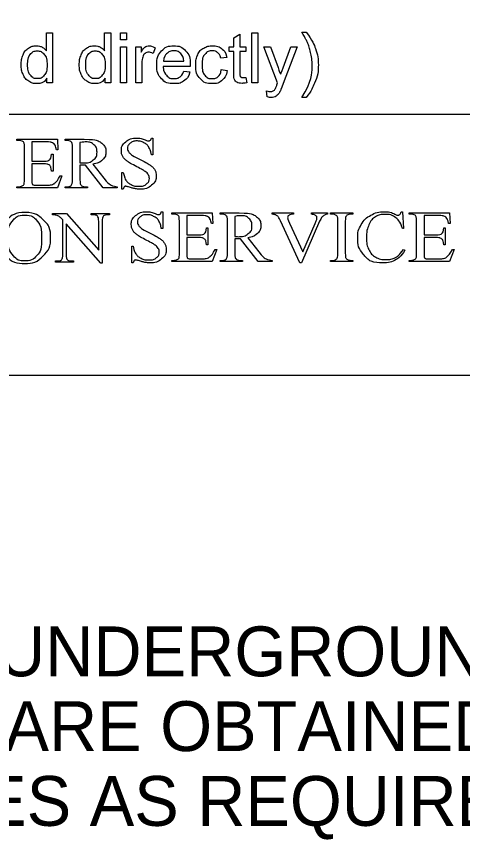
# Model space of a CAD drawing. Extents: x 0 to 34, y 0 to 22.
# Drawn here: x 5.69 to 6.942, y 7.479 to 9.791 of the extents above; entities that cross this region are included whole.
import ezdxf

# ---------------------------------------------------------------- set-up
doc = ezdxf.new("R2010")
doc.units = 0
doc.layers.add('SH_Data', color=7, linetype='Continuous')
doc.layers.add('SH_Text', color=7, linetype='Continuous')

msp = doc.modelspace()

# ---------------------------------------------------------------- linework, layer by layer
at = {"layer": 'SH_Data'}
msp.add_line((2.2617, 9.5165), (7.4617, 9.5165), dxfattribs=at)
msp.add_lwpolyline([(2.2617, 11.8822), (7.4617, 11.8822), (7.4617, 8.7822), (2.2617, 8.7822)], close=True, dxfattribs=at)
msp.add_lwpolyline([(2.2617, 11.8822), (7.4617, 11.8822), (7.4617, 8.7822), (2.2617, 8.7822)], close=True, dxfattribs=at)
for points in [[(5.7741, 9.6943), (5.7741, 9.7445), (5.7913, 9.7445), (5.7913, 9.6045), (5.7754, 9.6045)], [(5.9372, 9.6943), (5.9372, 9.7445), (5.9544, 9.7445), (5.9544, 9.6045), (5.9385, 9.6045)], [(5.9815, 9.7248), (5.9815, 9.7445), (5.9987, 9.7445), (5.9987, 9.7248), (5.9815, 9.7248)], [(6.2996, 9.6342), (6.2996, 9.6927), (6.2869, 9.6927), (6.2869, 9.706), (6.2996, 9.706), (6.2996, 9.7311), (6.3167, 9.7414), (6.3167, 9.706), (6.3339, 9.706), (6.3339, 9.6927), (6.3167, 9.6927), (6.3167, 9.6332)], [(6.3504, 9.6045), (6.3504, 9.7445), (6.3675, 9.7445), (6.3675, 9.6045), (6.3504, 9.6045)], [(6.491, 9.7469), (6.5033, 9.7469)], [(5.9815, 9.6045), (5.9815, 9.706), (5.9987, 9.706), (5.9987, 9.6045), (5.9815, 9.6045)], [(6.0246, 9.6045), (6.0246, 9.706), (6.0401, 9.706), (6.0401, 9.6906)], [(6.0796, 9.7028), (6.0736, 9.6868)], [(6.4229, 9.6044), (6.3844, 9.706), (6.4029, 9.706), (6.424, 9.6474)], [(6.4385, 9.6468), (6.4602, 9.706), (6.4774, 9.706), (6.4389, 9.6028)], [(6.1028, 9.6649), (6.1595, 9.6649)], [(6.2801, 9.6761), (6.2634, 9.6736)], [(6.0418, 9.6577), (6.0418, 9.6045), (6.0246, 9.6045)], [(6.1775, 9.6508), (6.1018, 9.6508)], [(6.2649, 9.6417), (6.2817, 9.6394)], [(5.7754, 9.6045), (5.7754, 9.6173)], [(5.9385, 9.6045), (5.9385, 9.6173)], [(6.1593, 9.6373), (6.177, 9.635)], [(6.3339, 9.6198), (6.3364, 9.6047)], [(6.3935, 9.5655), (6.3916, 9.5817)], [(6.5033, 9.5633), (6.491, 9.5633)], [(5.6966, 9.4424), (5.6914, 9.4424), (5.6914, 9.4461), (5.8048, 9.4461), (5.8063, 9.416), (5.8021, 9.416)], [(5.7332, 9.4386), (5.7332, 9.3846), (5.7655, 9.3846)], [(5.7736, 9.4386), (5.7332, 9.4386)], [(5.8319, 9.4424), (5.8264, 9.4424), (5.8264, 9.4461), (5.8798, 9.4461)], [(5.8681, 9.4365), (5.8681, 9.3795)], [(6.0725, 9.4492), (6.0725, 9.4019), (6.0685, 9.4019)], [(6.0685, 9.4492), (6.0725, 9.4492)], [(5.7124, 9.3335), (5.7124, 9.4223)], [(5.8474, 9.3335), (5.8474, 9.4218)], [(5.7887, 9.4045), (5.7926, 9.4045), (5.7926, 9.3567), (5.7887, 9.3567)], [(5.7655, 9.3771), (5.7332, 9.3771), (5.7332, 9.332)], [(5.8681, 9.3732), (5.8681, 9.3335)], [(5.9725, 9.3092), (5.9332, 9.3092), (5.8834, 9.3732)], [(5.9047, 9.3758), (5.9351, 9.3366)], [(5.813, 9.3435), (5.8174, 9.3435), (5.8047, 9.3092), (5.6914, 9.3092), (5.6914, 9.3129), (5.6966, 9.3129)], [(5.9899, 9.3061), (5.9859, 9.3061), (5.9859, 9.353), (5.9899, 9.353)], [(5.7453, 9.3167), (5.7703, 9.3167)], [(5.8834, 9.3129), (5.8891, 9.3129), (5.8891, 9.3092), (5.8264, 9.3092), (5.8264, 9.3129), (5.8319, 9.3129)], [(5.9725, 9.3129), (5.9725, 9.3092)], [(5.7911, 9.2374), (5.8308, 9.2374), (5.9208, 9.1347), (5.9208, 9.2137)], [(5.7911, 9.2337), (5.7911, 9.2374)], [(5.9051, 9.2337), (5.9, 9.2337), (5.9, 9.2374), (5.951, 9.2374), (5.951, 9.2337), (5.9458, 9.2337)], [(6.1004, 9.2423), (6.1004, 9.195), (6.0964, 9.195)], [(6.0964, 9.2423), (6.1004, 9.2423)], [(6.1315, 9.2355), (6.1263, 9.2355), (6.1263, 9.2391), (6.2396, 9.2391), (6.2412, 9.2091), (6.237, 9.2091)], [(6.1681, 9.2317), (6.1681, 9.1776), (6.2004, 9.1776)], [(6.2085, 9.2317), (6.1681, 9.2317)], [(6.2668, 9.2355), (6.2613, 9.2355), (6.2613, 9.2391), (6.3147, 9.2391)], [(6.303, 9.2295), (6.303, 9.1726)], [(6.4074, 9.2355), (6.4074, 9.2391), (6.4674, 9.2391), (6.4674, 9.2355)], [(6.5176, 9.2355), (6.5176, 9.2391), (6.5628, 9.2391)], [(6.5628, 9.2391), (6.5628, 9.2355)], [(6.5763, 9.2355), (6.5711, 9.2355), (6.5711, 9.2391), (6.6339, 9.2391), (6.6339, 9.2355), (6.6286, 9.2355)], [(6.7693, 9.2423), (6.7732, 9.2423)], [(6.7732, 9.2423), (6.7765, 9.1958), (6.7732, 9.1958)], [(6.7973, 9.2355), (6.7921, 9.2355), (6.7921, 9.2391), (6.9054, 9.2391), (6.907, 9.2091), (6.9028, 9.2091)], [(6.8339, 9.2317), (6.8339, 9.1776), (6.8662, 9.1776)], [(6.8743, 9.2317), (6.8339, 9.2317)], [(5.82, 9.1243), (5.82, 9.2194)], [(5.9303, 9.2137), (5.9303, 9.0983), (5.9264, 9.0983), (5.8295, 9.2086), (5.8295, 9.1243)], [(6.1473, 9.1265), (6.1473, 9.2153)], [(6.2823, 9.1265), (6.2823, 9.2149)], [(6.5408, 9.2157), (6.4897, 9.0991), (6.4857, 9.0991), (6.4307, 9.2172)], [(6.4561, 9.2105), (6.4935, 9.1302), (6.5281, 9.2095)], [(6.5921, 9.1265), (6.5921, 9.2149)], [(6.6129, 9.2149), (6.6129, 9.1265)], [(6.8131, 9.1265), (6.8131, 9.2153)], [(6.2236, 9.1975), (6.2275, 9.1975), (6.2275, 9.1498), (6.2236, 9.1498)], [(6.8894, 9.1975), (6.8933, 9.1975), (6.8933, 9.1498), (6.8894, 9.1498)], [(6.2004, 9.1701), (6.1681, 9.1701), (6.1681, 9.1251)], [(6.303, 9.1662), (6.303, 9.1265)], [(6.4074, 9.1023), (6.3681, 9.1023), (6.3183, 9.1662)], [(6.3396, 9.1689), (6.37, 9.1297)], [(6.8662, 9.1701), (6.8339, 9.1701), (6.8339, 9.1251)], [(6.0178, 9.0991), (6.0138, 9.0991), (6.0138, 9.1461), (6.0178, 9.1461)], [(6.2479, 9.1366), (6.2523, 9.1366), (6.2396, 9.1023), (6.1263, 9.1023), (6.1263, 9.106), (6.1315, 9.106)], [(6.7765, 9.1364), (6.7799, 9.1344)], [(6.9137, 9.1366), (6.9181, 9.1366), (6.9054, 9.1023), (6.7921, 9.1023), (6.7921, 9.106), (6.7973, 9.106)], [(6.1802, 9.1098), (6.2052, 9.1098)], [(6.846, 9.1098), (6.871, 9.1098)], [(5.8451, 9.1042), (5.8503, 9.1042), (5.8503, 9.1006), (5.7993, 9.1006), (5.7993, 9.1042), (5.8044, 9.1042)], [(6.3183, 9.106), (6.324, 9.106), (6.324, 9.1023), (6.2613, 9.1023), (6.2613, 9.106), (6.2668, 9.106)], [(6.4074, 9.106), (6.4074, 9.1023)], [(6.6339, 9.106), (6.6339, 9.1023), (6.5711, 9.1023), (6.5711, 9.106), (6.5763, 9.106)], [(6.6286, 9.106), (6.6339, 9.106)]]:
    msp.add_lwpolyline(points, dxfattribs=at)
for points in [[(6.491, 9.5633), (6.5195, 9.6092), (6.5195, 9.6551), (6.5195, 9.6731), (6.5154, 9.6907), (6.5122, 9.705), (6.5063, 9.7182), (6.5026, 9.7268), (6.491, 9.7469)], [(6.5033, 9.7469), (6.5212, 9.7229), (6.5298, 9.6987), (6.5372, 9.6779), (6.5372, 9.6552), (6.5372, 9.6294), (6.5273, 9.6053), (6.5174, 9.5813), (6.5033, 9.5633)], [(5.7754, 9.6173), (5.7658, 9.6023), (5.7471, 9.6023), (5.7349, 9.6023), (5.7247, 9.609), (5.7146, 9.6156), (5.709, 9.6276), (5.7034, 9.6396), (5.7034, 9.6552), (5.7034, 9.6703), (5.7084, 9.6827), (5.7135, 9.6951), (5.7236, 9.7017), (5.7337, 9.7082), (5.7462, 9.7082), (5.7554, 9.7082), (5.7625, 9.7044), (5.7697, 9.7005), (5.7741, 9.6943)], [(5.9385, 9.6173), (5.9288, 9.6023), (5.9101, 9.6023), (5.898, 9.6023), (5.8878, 9.609), (5.8776, 9.6156), (5.872, 9.6276), (5.8664, 9.6396), (5.8664, 9.6552), (5.8664, 9.6703), (5.8715, 9.6827), (5.8766, 9.6951), (5.8867, 9.7017), (5.8968, 9.7082), (5.9093, 9.7082), (5.9184, 9.7082), (5.9256, 9.7044), (5.9327, 9.7005), (5.9372, 9.6943)], [(6.0401, 9.6906), (6.046, 9.7014), (6.051, 9.7048), (6.056, 9.7082), (6.062, 9.7082), (6.0707, 9.7082), (6.0796, 9.7028)], [(6.177, 9.635), (6.1728, 9.6195), (6.1615, 9.6109), (6.1501, 9.6023), (6.1324, 9.6023), (6.1102, 9.6023), (6.0972, 9.616), (6.0841, 9.6297), (6.0841, 9.6544), (6.0841, 9.68), (6.0973, 9.6941), (6.1105, 9.7082), (6.1315, 9.7082), (6.1518, 9.7082), (6.1647, 9.6944), (6.1776, 9.6805), (6.1776, 9.6554), (6.1776, 9.6539), (6.1775, 9.6508)], [(6.2817, 9.6394), (6.279, 9.622), (6.2676, 9.6121), (6.2562, 9.6023), (6.2395, 9.6023), (6.2187, 9.6023), (6.2061, 9.6159), (6.1934, 9.6295), (6.1934, 9.6549), (6.1934, 9.6713), (6.1988, 9.6836), (6.2043, 9.6959), (6.2154, 9.7021), (6.2265, 9.7082), (6.2396, 9.7082), (6.2562, 9.7082), (6.2667, 9.6999), (6.2772, 9.6915), (6.2801, 9.6761)], [(5.7211, 9.6552), (5.7211, 9.6357), (5.7293, 9.626), (5.7375, 9.6164), (5.7487, 9.6164), (5.76, 9.6164), (5.7679, 9.6256), (5.7757, 9.6348), (5.7757, 9.6537), (5.7757, 9.6746), (5.7677, 9.6843), (5.7597, 9.694), (5.7479, 9.694), (5.7365, 9.694), (5.7288, 9.6847), (5.7211, 9.6753), (5.7211, 9.6552)], [(5.8842, 9.6552), (5.8842, 9.6357), (5.8924, 9.626), (5.9006, 9.6164), (5.9118, 9.6164), (5.923, 9.6164), (5.9309, 9.6256), (5.9388, 9.6348), (5.9388, 9.6537), (5.9388, 9.6746), (5.9308, 9.6843), (5.9227, 9.694), (5.911, 9.694), (5.8995, 9.694), (5.8918, 9.6847), (5.8842, 9.6753), (5.8842, 9.6552)], [(6.0736, 9.6868), (6.0674, 9.6905), (6.0611, 9.6905), (6.0555, 9.6905), (6.051, 9.6871), (6.0465, 9.6837), (6.0446, 9.6777), (6.0418, 9.6685), (6.0418, 9.6577)], [(6.1595, 9.6649), (6.1583, 9.6778), (6.153, 9.6842), (6.1447, 9.6942), (6.1317, 9.6942), (6.1198, 9.6942), (6.1117, 9.6862), (6.1037, 9.6782), (6.1028, 9.6649)], [(6.2634, 9.6736), (6.261, 9.6838), (6.255, 9.689), (6.2489, 9.6942), (6.2403, 9.6942), (6.2273, 9.6942), (6.2192, 9.6848), (6.2111, 9.6755), (6.2111, 9.6554), (6.2111, 9.6349), (6.2189, 9.6256), (6.2268, 9.6164), (6.2394, 9.6164), (6.2495, 9.6164), (6.2563, 9.6226), (6.2631, 9.6288), (6.2649, 9.6417)], [(6.1018, 9.6508), (6.1028, 9.6341), (6.1113, 9.6252), (6.1198, 9.6164), (6.1325, 9.6164), (6.142, 9.6164), (6.1487, 9.6214), (6.1554, 9.6263), (6.1593, 9.6373)], [(6.424, 9.6474), (6.4281, 9.6363), (6.4314, 9.624), (6.4344, 9.6356), (6.4385, 9.6468)], [(6.3364, 9.6047), (6.3291, 9.6031), (6.3234, 9.6031), (6.3141, 9.6031), (6.3089, 9.6061), (6.3038, 9.6091), (6.3017, 9.6139), (6.2996, 9.6187), (6.2996, 9.6342)], [(6.3167, 9.6332), (6.3167, 9.6258), (6.3177, 9.6237), (6.3186, 9.6216), (6.3206, 9.6204), (6.3226, 9.6191), (6.3264, 9.6191), (6.3293, 9.6191), (6.3339, 9.6198)], [(6.3916, 9.5817), (6.3972, 9.5802), (6.4014, 9.5802), (6.4071, 9.5802), (6.4105, 9.5821), (6.414, 9.584), (6.4162, 9.5874), (6.4178, 9.59), (6.4214, 9.6002), (6.4219, 9.6017), (6.4229, 9.6044)], [(6.4389, 9.6028), (6.4326, 9.5861), (6.4292, 9.5798), (6.4246, 9.5713), (6.4187, 9.5674), (6.4128, 9.5634), (6.4046, 9.5634), (6.3996, 9.5634), (6.3935, 9.5655)], [(5.7124, 9.4223), (5.7124, 9.4353), (5.7096, 9.4383), (5.7057, 9.4424), (5.6966, 9.4424)], [(5.8021, 9.416), (5.7998, 9.4268), (5.7971, 9.4309), (5.7943, 9.4349), (5.7889, 9.4371), (5.7845, 9.4386), (5.7736, 9.4386)], [(5.8474, 9.4218), (5.8474, 9.4348), (5.8444, 9.4379), (5.8402, 9.4424), (5.8319, 9.4424)], [(5.8681, 9.3795), (5.8702, 9.3795), (5.8717, 9.3795), (5.8732, 9.3794), (5.8741, 9.3794), (5.8949, 9.3794), (5.9055, 9.3879), (5.916, 9.3964), (5.916, 9.4095), (5.916, 9.4223), (5.9075, 9.4303), (5.899, 9.4384), (5.885, 9.4384), (5.8787, 9.4384), (5.8681, 9.4365)], [(5.8798, 9.4461), (5.9032, 9.4461), (5.9143, 9.4429), (5.9254, 9.4397), (5.9331, 9.4312), (5.9409, 9.4227), (5.9409, 9.4108), (5.9409, 9.3982), (5.932, 9.3889), (5.9232, 9.3796), (5.9047, 9.3758)], [(5.9899, 9.353), (5.9927, 9.3383), (5.9975, 9.3309), (6.0022, 9.3236), (6.012, 9.3188), (6.0219, 9.3139), (6.0336, 9.3139), (6.0471, 9.3139), (6.055, 9.3206), (6.0629, 9.3273), (6.0629, 9.3364), (6.0629, 9.3414), (6.0599, 9.3466), (6.0569, 9.3517), (6.0506, 9.3562), (6.0464, 9.3592), (6.0275, 9.369), (6.0086, 9.3789), (6.0006, 9.3847), (5.9926, 9.3906), (5.9885, 9.3976), (5.9843, 9.4047), (5.9843, 9.4132), (5.9843, 9.4279), (5.9965, 9.4386), (6.0087, 9.4492), (6.0275, 9.4492), (6.0393, 9.4492), (6.0524, 9.4439), (6.0585, 9.4414), (6.061, 9.4414), (6.0638, 9.4414), (6.0656, 9.4429), (6.0674, 9.4445), (6.0685, 9.4492)], [(6.0685, 9.4019), (6.0665, 9.4155), (6.0615, 9.4236), (6.0564, 9.4317), (6.0471, 9.4364), (6.0377, 9.4412), (6.0277, 9.4412), (6.0164, 9.4412), (6.009, 9.4348), (6.0016, 9.4283), (6.0016, 9.4202), (6.0016, 9.4139), (6.0063, 9.4087), (6.013, 9.4012), (6.0383, 9.3885), (6.059, 9.3782), (6.0665, 9.3727), (6.074, 9.3672), (6.0781, 9.3598), (6.0822, 9.3523), (6.0822, 9.3441), (6.0822, 9.3286), (6.0692, 9.3173), (6.0563, 9.3061), (6.0359, 9.3061), (6.0295, 9.3061), (6.0238, 9.307), (6.0205, 9.3075), (6.0099, 9.3107), (5.9993, 9.3139), (5.9965, 9.3139), (5.9938, 9.3139), (5.9922, 9.3124), (5.9906, 9.3108), (5.9899, 9.3061)], [(5.7655, 9.3846), (5.7781, 9.3846), (5.7824, 9.3881), (5.788, 9.3928), (5.7887, 9.4045)], [(5.7887, 9.3567), (5.7871, 9.3667), (5.7856, 9.3695), (5.7837, 9.3731), (5.7792, 9.3751), (5.7747, 9.3771), (5.7655, 9.3771)], [(5.8834, 9.3732), (5.8779, 9.373), (5.8745, 9.373), (5.8731, 9.373), (5.8715, 9.373), (5.8699, 9.3731), (5.8681, 9.3732)], [(5.7703, 9.3167), (5.7828, 9.3167), (5.7884, 9.3183), (5.7941, 9.3199), (5.7993, 9.3247), (5.806, 9.3309), (5.813, 9.3435)], [(5.6966, 9.3129), (5.7018, 9.3129), (5.7065, 9.3152), (5.7099, 9.3169), (5.7112, 9.3201), (5.7124, 9.3234), (5.7124, 9.3335)], [(5.7332, 9.332), (5.7332, 9.3229), (5.7341, 9.321), (5.7349, 9.319), (5.7371, 9.3179), (5.7393, 9.3167), (5.7453, 9.3167)], [(5.8319, 9.3129), (5.8411, 9.3129), (5.8451, 9.3186), (5.8474, 9.3217), (5.8474, 9.3335)], [(5.8681, 9.3335), (5.8681, 9.3205), (5.8712, 9.3174), (5.8752, 9.3129), (5.8834, 9.3129)], [(5.9351, 9.3366), (5.9455, 9.323), (5.953, 9.3186), (5.9605, 9.3141), (5.9725, 9.3129)], [(5.7149, 9.2406), (5.7435, 9.2406), (5.7645, 9.2203), (5.7855, 9.2001), (5.7855, 9.1698), (5.7855, 9.1386), (5.7643, 9.118), (5.7432, 9.0974), (5.7132, 9.0974), (5.6828, 9.0974), (5.6622, 9.1175), (5.6415, 9.1376), (5.6415, 9.1695), (5.6415, 9.2021), (5.6654, 9.2227), (5.6861, 9.2406), (5.7149, 9.2406)], [(5.7128, 9.2332), (5.6931, 9.2332), (5.6812, 9.2196), (5.6664, 9.2026), (5.6664, 9.1699), (5.6664, 9.1364), (5.6818, 9.1183), (5.6936, 9.1046), (5.713, 9.1046), (5.7336, 9.1046), (5.7471, 9.1196), (5.7606, 9.1347), (5.7606, 9.1671), (5.7606, 9.2022), (5.7458, 9.2195), (5.7339, 9.2332), (5.7128, 9.2332)], [(5.82, 9.2194), (5.8136, 9.2264), (5.8103, 9.2287), (5.807, 9.2309), (5.8006, 9.2328), (5.7975, 9.2337), (5.7911, 9.2337)], [(5.9208, 9.2137), (5.9208, 9.2264), (5.9177, 9.2295), (5.9137, 9.2337), (5.9051, 9.2337)], [(5.9458, 9.2337), (5.9365, 9.2337), (5.9326, 9.2285), (5.9303, 9.2253), (5.9303, 9.2137)], [(6.0178, 9.1461), (6.0206, 9.1313), (6.0254, 9.124), (6.0302, 9.1167), (6.04, 9.1118), (6.0498, 9.107), (6.0615, 9.107), (6.0751, 9.107), (6.0829, 9.1136), (6.0908, 9.1203), (6.0908, 9.1294), (6.0908, 9.1345), (6.0878, 9.1396), (6.0848, 9.1448), (6.0785, 9.1492), (6.0743, 9.1523), (6.0554, 9.1621), (6.0365, 9.1719), (6.0285, 9.1778), (6.0205, 9.1836), (6.0164, 9.1907), (6.0123, 9.1978), (6.0123, 9.2062), (6.0123, 9.221), (6.0244, 9.2316), (6.0366, 9.2423), (6.0554, 9.2423), (6.0672, 9.2423), (6.0803, 9.237), (6.0864, 9.2345), (6.0889, 9.2345), (6.0918, 9.2345), (6.0935, 9.236), (6.0953, 9.2376), (6.0964, 9.2423)], [(6.0964, 9.195), (6.0945, 9.2086), (6.0894, 9.2167), (6.0844, 9.2247), (6.075, 9.2295), (6.0657, 9.2342), (6.0557, 9.2342), (6.0443, 9.2342), (6.037, 9.2278), (6.0296, 9.2214), (6.0296, 9.2132), (6.0296, 9.207), (6.0342, 9.2018), (6.041, 9.1942), (6.0663, 9.1816), (6.0869, 9.1713), (6.0944, 9.1658), (6.102, 9.1603), (6.106, 9.1528), (6.1101, 9.1454), (6.1101, 9.1372), (6.1101, 9.1216), (6.0971, 9.1104), (6.0842, 9.0991), (6.0638, 9.0991), (6.0574, 9.0991), (6.0517, 9.1), (6.0484, 9.1006), (6.0378, 9.1038), (6.0272, 9.107), (6.0244, 9.107), (6.0217, 9.107), (6.0201, 9.1054), (6.0186, 9.1039), (6.0178, 9.0991)], [(6.1473, 9.2153), (6.1473, 9.2284), (6.1445, 9.2314), (6.1406, 9.2355), (6.1315, 9.2355)], [(6.237, 9.2091), (6.2347, 9.2199), (6.232, 9.224), (6.2292, 9.228), (6.2238, 9.2301), (6.2194, 9.2317), (6.2085, 9.2317)], [(6.2823, 9.2149), (6.2823, 9.2279), (6.2792, 9.231), (6.275, 9.2355), (6.2668, 9.2355)], [(6.303, 9.1726), (6.3051, 9.1726), (6.3066, 9.1726), (6.3081, 9.1725), (6.309, 9.1725), (6.3298, 9.1725), (6.3404, 9.181), (6.3509, 9.1895), (6.3509, 9.2026), (6.3509, 9.2154), (6.3424, 9.2234), (6.3339, 9.2314), (6.3199, 9.2314), (6.3136, 9.2314), (6.303, 9.2295)], [(6.3147, 9.2391), (6.3381, 9.2391), (6.3492, 9.236), (6.3603, 9.2328), (6.368, 9.2243), (6.3758, 9.2157), (6.3758, 9.2039), (6.3758, 9.1913), (6.3669, 9.182), (6.3581, 9.1727), (6.3396, 9.1689)], [(6.4307, 9.2172), (6.4265, 9.2263), (6.4247, 9.2283), (6.422, 9.2314), (6.4181, 9.2332), (6.4141, 9.235), (6.4074, 9.2355)], [(6.4674, 9.2355), (6.4572, 9.2345), (6.4541, 9.2322), (6.4511, 9.2299), (6.4511, 9.2263), (6.4511, 9.2212), (6.4561, 9.2105)], [(6.5281, 9.2095), (6.5332, 9.2212), (6.5332, 9.2258), (6.5332, 9.2287), (6.5301, 9.2314), (6.5269, 9.234), (6.5195, 9.2352), (6.5189, 9.2353), (6.5176, 9.2355)], [(6.5628, 9.2355), (6.555, 9.2341), (6.551, 9.2308), (6.5452, 9.2259), (6.5408, 9.2157)], [(6.5921, 9.2149), (6.5921, 9.2253), (6.5907, 9.2287), (6.5896, 9.2312), (6.5863, 9.233), (6.5815, 9.2355), (6.5763, 9.2355)], [(6.6286, 9.2355), (6.6197, 9.2355), (6.6156, 9.2305), (6.6129, 9.2272), (6.6129, 9.2149)], [(6.7799, 9.1344), (6.7688, 9.1161), (6.7541, 9.1076), (6.7394, 9.0991), (6.7191, 9.0991), (6.6827, 9.0991), (6.6626, 9.1244), (6.6477, 9.1431), (6.6477, 9.1686), (6.6477, 9.1891), (6.6575, 9.2062), (6.6674, 9.2234), (6.6846, 9.2328), (6.7019, 9.2423), (6.7224, 9.2423), (6.7383, 9.2423), (6.7537, 9.235), (6.7583, 9.2328), (6.7602, 9.2328), (6.7631, 9.2328), (6.7653, 9.2347), (6.7681, 9.2374), (6.7693, 9.2423)], [(6.7732, 9.1958), (6.7665, 9.2167), (6.754, 9.2259), (6.7416, 9.2351), (6.7242, 9.2351), (6.7096, 9.2351), (6.6978, 9.2282), (6.6861, 9.2213), (6.6793, 9.2061), (6.6726, 9.1909), (6.6726, 9.1684), (6.6726, 9.1498), (6.6789, 9.1362), (6.6853, 9.1225), (6.6981, 9.1152), (6.7109, 9.108), (6.7273, 9.108), (6.7416, 9.108), (6.7525, 9.1137), (6.7634, 9.1194), (6.7765, 9.1364)], [(6.8131, 9.2153), (6.8131, 9.2284), (6.8103, 9.2314), (6.8064, 9.2355), (6.7973, 9.2355)], [(6.9028, 9.2091), (6.9005, 9.2199), (6.8978, 9.224), (6.895, 9.228), (6.8896, 9.2301), (6.8852, 9.2317), (6.8743, 9.2317)], [(6.2004, 9.1776), (6.213, 9.1776), (6.2173, 9.1812), (6.2229, 9.1858), (6.2236, 9.1975)], [(6.8662, 9.1776), (6.8788, 9.1776), (6.8831, 9.1812), (6.8887, 9.1858), (6.8894, 9.1975)], [(6.2236, 9.1498), (6.222, 9.1598), (6.2205, 9.1626), (6.2186, 9.1661), (6.2141, 9.1681), (6.2096, 9.1701), (6.2004, 9.1701)], [(6.3183, 9.1662), (6.3128, 9.166), (6.3094, 9.166), (6.308, 9.166), (6.3064, 9.1661), (6.3048, 9.1661), (6.303, 9.1662)], [(6.8894, 9.1498), (6.8878, 9.1598), (6.8863, 9.1626), (6.8844, 9.1661), (6.8799, 9.1681), (6.8754, 9.1701), (6.8662, 9.1701)], [(6.2052, 9.1098), (6.2177, 9.1098), (6.2233, 9.1114), (6.2289, 9.113), (6.2342, 9.1177), (6.2409, 9.124), (6.2479, 9.1366)], [(6.871, 9.1098), (6.8835, 9.1098), (6.8891, 9.1114), (6.8947, 9.113), (6.9, 9.1177), (6.9067, 9.124), (6.9137, 9.1366)], [(5.8044, 9.1042), (5.8138, 9.1042), (5.8177, 9.1095), (5.82, 9.1127), (5.82, 9.1243)], [(5.8295, 9.1243), (5.8295, 9.1116), (5.8324, 9.1085), (5.8366, 9.1042), (5.8451, 9.1042)], [(6.1315, 9.106), (6.1367, 9.106), (6.1414, 9.1083), (6.1448, 9.1099), (6.1461, 9.1132), (6.1473, 9.1164), (6.1473, 9.1265)], [(6.1681, 9.1251), (6.1681, 9.116), (6.169, 9.114), (6.1698, 9.1121), (6.172, 9.1109), (6.1742, 9.1098), (6.1802, 9.1098)], [(6.2668, 9.106), (6.276, 9.106), (6.28, 9.1116), (6.2823, 9.1148), (6.2823, 9.1265)], [(6.303, 9.1265), (6.303, 9.1136), (6.3061, 9.1104), (6.3101, 9.106), (6.3183, 9.106)], [(6.37, 9.1297), (6.3804, 9.1161), (6.3879, 9.1116), (6.3954, 9.1072), (6.4074, 9.106)], [(6.5763, 9.106), (6.5854, 9.106), (6.5895, 9.1109), (6.5921, 9.1142), (6.5921, 9.1265)], [(6.6129, 9.1265), (6.6129, 9.1161), (6.6143, 9.1127), (6.6154, 9.1102), (6.6188, 9.1084), (6.6234, 9.106), (6.6286, 9.106)], [(6.7973, 9.106), (6.8025, 9.106), (6.8072, 9.1083), (6.8106, 9.1099), (6.8119, 9.1132), (6.8131, 9.1164), (6.8131, 9.1265)], [(6.8339, 9.1251), (6.8339, 9.116), (6.8348, 9.114), (6.8356, 9.1121), (6.8378, 9.1109), (6.84, 9.1098), (6.846, 9.1098)]]:
    msp.add_open_spline(points, degree=3, dxfattribs=at)

# ---------------------------------------------------------------- texts
at = {"layer": 'SH_Text'}
for s, p in [('THE LOCATION OF THE UNDERGROUND UTILITIES', (3.4617, 7.9379)), ('SHOWN ON THE PLANS ARE OBTAINED FROM THE', (3.4617, 7.7279)), ('OWNER OF THE UTILITIES AS REQUIRED BY', (3.4617, 7.5179))]:
    msp.add_text(s, height=0.14, dxfattribs=at).set_placement(p)

doc.saveas('drawing.dxf')
